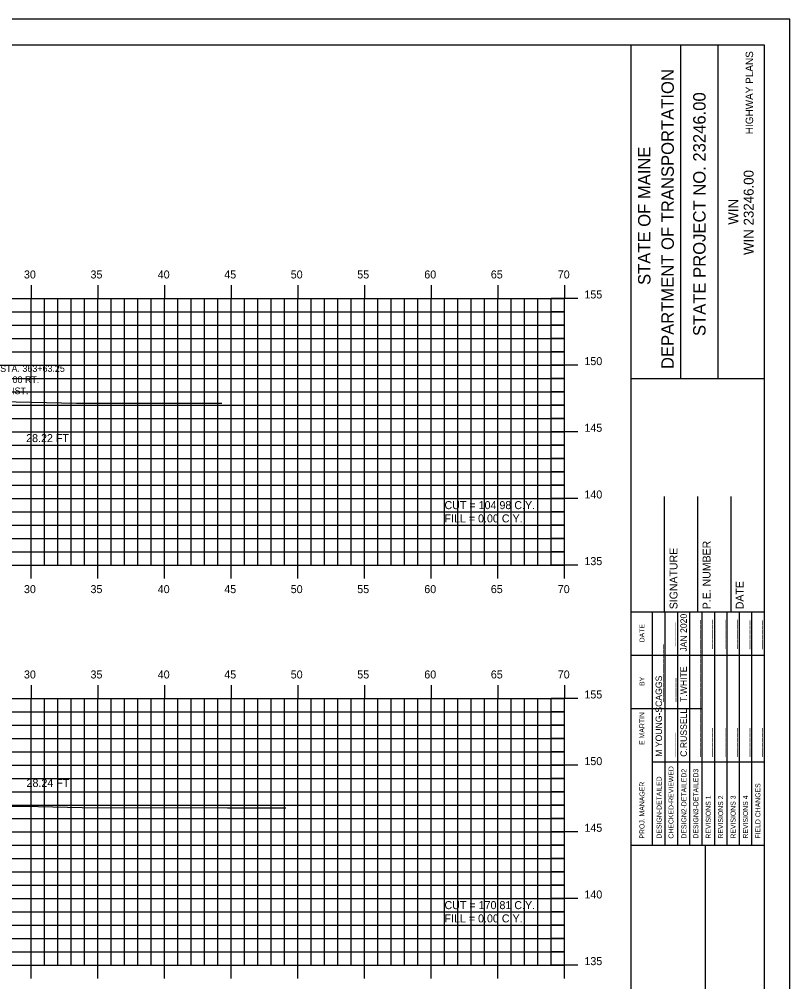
# Model space of a CAD drawing. Extents: x 1146968 to 1147138, y 608981 to 609091.
# Drawn here: x 1147080.3 to 1147138.1, y 609019.1 to 609091.3 of the extents above; entities that cross this region are included whole.
import ezdxf

# ---------------------------------------------------------------- set-up
doc = ezdxf.new("R2010")
doc.units = 0
for name, color, linetype in [('BORDER', 7, 'Continuous'), ('D_Text_Monospaced', 7, 'Continuous'), ('D_Text_Standard', 7, 'Continuous'), ('H_V ANNOTATION', 7, 'Continuous'), ('HIGHWAY_TITLE', 7, 'Continuous'), ('MAJOR', 7, 'Continuous'), ('MINOR', 7, 'Continuous'), ('PLOT BOUNDARY', 7, 'Continuous'), ('S_Roadway_Centerline', 7, 'Continuous')]:
    doc.layers.add(name, color=color, linetype=linetype)

msp = doc.modelspace()

# ---------------------------------------------------------------- linework, layer by layer
at = {"layer": 'BORDER'}
for p, q in [((1147126.185, 608984.335), (1147126.185, 609089.335)), ((1147129.913, 609064.332), (1147129.913, 609089.332)), ((1147132.708, 609064.332), (1147132.708, 609089.332)), ((1147126.185, 609064.329), (1147136.185, 609064.329)), ((1147128.685, 609046.838), (1147128.685, 609055.485)), ((1147131.185, 609046.838), (1147131.185, 609055.485)), ((1147133.685, 609046.838), (1147133.685, 609055.485)), ((1147126.185, 609046.838), (1147136.185, 609046.838)), ((1147126.185, 609029.338), (1147136.185, 609029.338)), ((1147131.776, 608994.338), (1147131.776, 609029.338))]:
    msp.add_line(p, q, dxfattribs=at)
msp.add_lwpolyline([(1146976.185, 608984.335), (1147136.185, 608984.335), (1147136.185, 609089.335), (1146976.185, 609089.335)], close=True, dxfattribs=at)
for points in [[(1147127.799, 609043.588), (1147127.799, 609046.838)], [(1147128.732, 609029.341), (1147128.732, 609046.838)], [(1147129.664, 609046.838), (1147129.664, 609029.341)], [(1147130.595, 609029.341), (1147130.595, 609046.838)], [(1147131.527, 609029.341), (1147131.527, 609046.838)], [(1147132.459, 609029.341), (1147132.459, 609046.838)], [(1147133.39, 609029.341), (1147133.39, 609046.838)], [(1147134.322, 609029.341), (1147134.322, 609046.838)], [(1147135.254, 609029.341), (1147135.254, 609046.838)], [(1147127.8, 609029.341), (1147127.8, 609046.132)], [(1147126.185, 609043.588), (1147136.185, 609043.588)], [(1147126.185, 609039.588), (1147127.8, 609039.588)], [(1147127.799, 609039.588), (1147131.526, 609039.588)], [(1147127.799, 609035.588), (1147136.185, 609035.588)]]:
    msp.add_lwpolyline(points, dxfattribs=at)
at = {"layer": 'MAJOR'}
for p, q in [((1147081.184, 609071.337), (1147081.184, 609070.335)), ((1147086.184, 609071.337), (1147086.184, 609070.335)), ((1147091.184, 609071.337), (1147091.184, 609070.335)), ((1147096.184, 609071.337), (1147096.184, 609070.335)), ((1147101.184, 609071.337), (1147101.184, 609070.335)), ((1147106.184, 609071.337), (1147106.184, 609070.335)), ((1147111.184, 609071.337), (1147111.184, 609070.335)), ((1147116.184, 609071.337), (1147116.184, 609070.335)), ((1147121.184, 609071.337), (1147121.184, 609070.335)), ((1146981.184, 609070.335), (1147121.184, 609070.335)), ((1146981.184, 609070.335), (1147121.184, 609070.335)), ((1147081.184, 609050.335), (1147081.184, 609070.335)), ((1147086.184, 609050.335), (1147086.184, 609070.335)), ((1147091.184, 609050.335), (1147091.184, 609070.335)), ((1147096.184, 609050.335), (1147096.184, 609070.335)), ((1147101.184, 609050.335), (1147101.184, 609070.335)), ((1147106.184, 609050.335), (1147106.184, 609070.335)), ((1147111.184, 609050.335), (1147111.184, 609070.335)), ((1147116.184, 609050.335), (1147116.184, 609070.335)), ((1147122.186, 609070.335), (1147120.182, 609070.335)), ((1147121.184, 609050.335), (1147121.184, 609070.335)), ((1147121.184, 609050.335), (1147121.184, 609070.335)), ((1146981.184, 609065.335), (1147121.184, 609065.335)), ((1147122.186, 609065.335), (1147120.182, 609065.335)), ((1146981.184, 609060.335), (1147121.184, 609060.335)), ((1147122.186, 609060.335), (1147120.182, 609060.335)), ((1146981.184, 609055.335), (1147121.184, 609055.335)), ((1147122.186, 609055.335), (1147120.182, 609055.335)), ((1146981.184, 609050.335), (1147121.184, 609050.335)), ((1146981.184, 609050.335), (1147121.184, 609050.335)), ((1147081.184, 609049.333), (1147081.184, 609050.335)), ((1147086.184, 609049.333), (1147086.184, 609050.335)), ((1147091.184, 609049.333), (1147091.184, 609050.335)), ((1147096.184, 609049.333), (1147096.184, 609050.335)), ((1147101.184, 609049.333), (1147101.184, 609050.335)), ((1147106.184, 609049.333), (1147106.184, 609050.335)), ((1147111.184, 609049.333), (1147111.184, 609050.335)), ((1147116.184, 609049.333), (1147116.184, 609050.335)), ((1147122.186, 609050.335), (1147120.182, 609050.335)), ((1147121.184, 609049.333), (1147121.184, 609050.335)), ((1147081.184, 609041.337), (1147081.184, 609040.335)), ((1147086.184, 609041.337), (1147086.184, 609040.335)), ((1147091.184, 609041.337), (1147091.184, 609040.335)), ((1147096.184, 609041.337), (1147096.184, 609040.335)), ((1147101.184, 609041.337), (1147101.184, 609040.335)), ((1147106.184, 609041.337), (1147106.184, 609040.335)), ((1147111.184, 609041.337), (1147111.184, 609040.335)), ((1147116.184, 609041.337), (1147116.184, 609040.335)), ((1147121.184, 609041.337), (1147121.184, 609040.335)), ((1146981.184, 609040.335), (1147121.184, 609040.335)), ((1146981.184, 609040.335), (1147121.184, 609040.335)), ((1147081.184, 609020.335), (1147081.184, 609040.335)), ((1147086.184, 609020.335), (1147086.184, 609040.335)), ((1147091.184, 609020.335), (1147091.184, 609040.335)), ((1147096.184, 609020.335), (1147096.184, 609040.335)), ((1147101.184, 609020.335), (1147101.184, 609040.335)), ((1147106.184, 609020.335), (1147106.184, 609040.335)), ((1147111.184, 609020.335), (1147111.184, 609040.335)), ((1147116.184, 609020.335), (1147116.184, 609040.335)), ((1147122.186, 609040.335), (1147120.182, 609040.335)), ((1147121.184, 609020.335), (1147121.184, 609040.335)), ((1147121.184, 609020.335), (1147121.184, 609040.335)), ((1146981.184, 609035.335), (1147121.184, 609035.335)), ((1147122.186, 609035.335), (1147120.182, 609035.335)), ((1146981.184, 609030.335), (1147121.184, 609030.335)), ((1147122.186, 609030.335), (1147120.182, 609030.335)), ((1146981.184, 609025.335), (1147121.184, 609025.335)), ((1147122.186, 609025.335), (1147120.182, 609025.335)), ((1146981.184, 609020.335), (1147121.184, 609020.335)), ((1146981.184, 609020.335), (1147121.184, 609020.335)), ((1147081.184, 609019.333), (1147081.184, 609020.335)), ((1147086.184, 609019.333), (1147086.184, 609020.335)), ((1147091.184, 609019.333), (1147091.184, 609020.335)), ((1147096.184, 609019.333), (1147096.184, 609020.335)), ((1147101.184, 609019.333), (1147101.184, 609020.335)), ((1147106.184, 609019.333), (1147106.184, 609020.335)), ((1147111.184, 609019.333), (1147111.184, 609020.335)), ((1147116.184, 609019.333), (1147116.184, 609020.335)), ((1147122.186, 609020.335), (1147120.182, 609020.335)), ((1147121.184, 609019.333), (1147121.184, 609020.335))]:
    msp.add_line(p, q, dxfattribs=at)
at = {"layer": 'MINOR'}
for p, q in [((1147082.184, 609050.335), (1147082.184, 609070.335)), ((1147083.184, 609050.335), (1147083.184, 609070.335)), ((1147084.184, 609050.335), (1147084.184, 609070.335)), ((1147085.184, 609050.335), (1147085.184, 609070.335)), ((1147087.184, 609050.335), (1147087.184, 609070.335)), ((1147088.184, 609050.335), (1147088.184, 609070.335)), ((1147089.184, 609050.335), (1147089.184, 609070.335)), ((1147090.184, 609050.335), (1147090.184, 609070.335)), ((1147092.184, 609050.335), (1147092.184, 609070.335)), ((1147093.184, 609050.335), (1147093.184, 609070.335)), ((1147094.184, 609050.335), (1147094.184, 609070.335)), ((1147095.184, 609050.335), (1147095.184, 609070.335)), ((1147097.184, 609050.335), (1147097.184, 609070.335)), ((1147098.184, 609050.335), (1147098.184, 609070.335)), ((1147099.184, 609050.335), (1147099.184, 609070.335)), ((1147100.184, 609050.335), (1147100.184, 609070.335)), ((1147102.184, 609050.335), (1147102.184, 609070.335)), ((1147103.184, 609050.335), (1147103.184, 609070.335)), ((1147104.184, 609050.335), (1147104.184, 609070.335)), ((1147105.184, 609050.335), (1147105.184, 609070.335)), ((1147107.184, 609050.335), (1147107.184, 609070.335)), ((1147108.184, 609050.335), (1147108.184, 609070.335)), ((1147109.184, 609050.335), (1147109.184, 609070.335)), ((1147110.184, 609050.335), (1147110.184, 609070.335)), ((1147112.184, 609050.335), (1147112.184, 609070.335)), ((1147113.184, 609050.335), (1147113.184, 609070.335)), ((1147114.184, 609050.335), (1147114.184, 609070.335)), ((1147115.184, 609050.335), (1147115.184, 609070.335)), ((1147117.184, 609050.335), (1147117.184, 609070.335)), ((1147118.184, 609050.335), (1147118.184, 609070.335)), ((1147119.184, 609050.335), (1147119.184, 609070.335)), ((1147120.184, 609050.335), (1147120.184, 609070.335)), ((1146981.184, 609069.335), (1147121.184, 609069.335)), ((1147121.184, 609069.335), (1147120.182, 609069.335)), ((1146981.184, 609068.335), (1147121.184, 609068.335)), ((1147121.184, 609068.335), (1147120.182, 609068.335)), ((1146981.184, 609067.335), (1147121.184, 609067.335)), ((1147121.184, 609067.335), (1147120.182, 609067.335)), ((1146981.184, 609066.335), (1147121.184, 609066.335)), ((1147121.184, 609066.335), (1147120.182, 609066.335)), ((1146981.184, 609064.335), (1147121.184, 609064.335)), ((1147121.184, 609064.335), (1147120.182, 609064.335)), ((1146981.184, 609063.335), (1147121.184, 609063.335)), ((1147121.184, 609063.335), (1147120.182, 609063.335)), ((1146981.184, 609062.335), (1147121.184, 609062.335)), ((1147121.184, 609062.335), (1147120.182, 609062.335)), ((1146981.184, 609061.335), (1147121.184, 609061.335)), ((1147121.184, 609061.335), (1147120.182, 609061.335)), ((1146981.184, 609059.335), (1147121.184, 609059.335)), ((1147121.184, 609059.335), (1147120.182, 609059.335)), ((1146981.184, 609058.335), (1147121.184, 609058.335)), ((1147121.184, 609058.335), (1147120.182, 609058.335)), ((1146981.184, 609057.335), (1147121.184, 609057.335)), ((1147121.184, 609057.335), (1147120.182, 609057.335)), ((1146981.184, 609056.335), (1147121.184, 609056.335)), ((1147121.184, 609056.335), (1147120.182, 609056.335)), ((1146981.184, 609054.335), (1147121.184, 609054.335)), ((1147121.184, 609054.335), (1147120.182, 609054.335)), ((1146981.184, 609053.335), (1147121.184, 609053.335)), ((1147121.184, 609053.335), (1147120.182, 609053.335)), ((1146981.184, 609052.335), (1147121.184, 609052.335)), ((1147121.184, 609052.335), (1147120.182, 609052.335)), ((1146981.184, 609051.335), (1147121.184, 609051.335)), ((1147121.184, 609051.335), (1147120.182, 609051.335)), ((1147082.184, 609020.335), (1147082.184, 609040.335)), ((1147083.184, 609020.335), (1147083.184, 609040.335)), ((1147084.184, 609020.335), (1147084.184, 609040.335)), ((1147085.184, 609020.335), (1147085.184, 609040.335)), ((1147087.184, 609020.335), (1147087.184, 609040.335)), ((1147088.184, 609020.335), (1147088.184, 609040.335)), ((1147089.184, 609020.335), (1147089.184, 609040.335)), ((1147090.184, 609020.335), (1147090.184, 609040.335)), ((1147092.184, 609020.335), (1147092.184, 609040.335)), ((1147093.184, 609020.335), (1147093.184, 609040.335)), ((1147094.184, 609020.335), (1147094.184, 609040.335)), ((1147095.184, 609020.335), (1147095.184, 609040.335)), ((1147097.184, 609020.335), (1147097.184, 609040.335)), ((1147098.184, 609020.335), (1147098.184, 609040.335)), ((1147099.184, 609020.335), (1147099.184, 609040.335)), ((1147100.184, 609020.335), (1147100.184, 609040.335)), ((1147102.184, 609020.335), (1147102.184, 609040.335)), ((1147103.184, 609020.335), (1147103.184, 609040.335)), ((1147104.184, 609020.335), (1147104.184, 609040.335)), ((1147105.184, 609020.335), (1147105.184, 609040.335)), ((1147107.184, 609020.335), (1147107.184, 609040.335)), ((1147108.184, 609020.335), (1147108.184, 609040.335)), ((1147109.184, 609020.335), (1147109.184, 609040.335)), ((1147110.184, 609020.335), (1147110.184, 609040.335)), ((1147112.184, 609020.335), (1147112.184, 609040.335)), ((1147113.184, 609020.335), (1147113.184, 609040.335)), ((1147114.184, 609020.335), (1147114.184, 609040.335)), ((1147115.184, 609020.335), (1147115.184, 609040.335)), ((1147117.184, 609020.335), (1147117.184, 609040.335)), ((1147118.184, 609020.335), (1147118.184, 609040.335)), ((1147119.184, 609020.335), (1147119.184, 609040.335)), ((1147120.184, 609020.335), (1147120.184, 609040.335)), ((1146981.184, 609039.335), (1147121.184, 609039.335)), ((1147121.184, 609039.335), (1147120.182, 609039.335)), ((1146981.184, 609038.335), (1147121.184, 609038.335)), ((1147121.184, 609038.335), (1147120.182, 609038.335)), ((1146981.184, 609037.335), (1147121.184, 609037.335)), ((1147121.184, 609037.335), (1147120.182, 609037.335)), ((1146981.184, 609036.335), (1147121.184, 609036.335)), ((1147121.184, 609036.335), (1147120.182, 609036.335)), ((1146981.184, 609034.335), (1147121.184, 609034.335)), ((1147121.184, 609034.335), (1147120.182, 609034.335)), ((1146981.184, 609033.335), (1147121.184, 609033.335)), ((1147121.184, 609033.335), (1147120.182, 609033.335)), ((1146981.184, 609032.335), (1147121.184, 609032.335)), ((1147121.184, 609032.335), (1147120.182, 609032.335)), ((1146981.184, 609031.335), (1147121.184, 609031.335)), ((1147121.184, 609031.335), (1147120.182, 609031.335)), ((1146981.184, 609029.335), (1147121.184, 609029.335)), ((1147121.184, 609029.335), (1147120.182, 609029.335)), ((1146981.184, 609028.335), (1147121.184, 609028.335)), ((1147121.184, 609028.335), (1147120.182, 609028.335)), ((1146981.184, 609027.335), (1147121.184, 609027.335)), ((1147121.184, 609027.335), (1147120.182, 609027.335)), ((1146981.184, 609026.335), (1147121.184, 609026.335)), ((1147121.184, 609026.335), (1147120.182, 609026.335)), ((1146981.184, 609024.335), (1147121.184, 609024.335)), ((1147121.184, 609024.335), (1147120.182, 609024.335)), ((1146981.184, 609023.335), (1147121.184, 609023.335)), ((1147121.184, 609023.335), (1147120.182, 609023.335)), ((1146981.184, 609022.335), (1147121.184, 609022.335)), ((1147121.184, 609022.335), (1147120.182, 609022.335)), ((1146981.184, 609021.335), (1147121.184, 609021.335)), ((1147121.184, 609021.335), (1147120.182, 609021.335))]:
    msp.add_line(p, q, dxfattribs=at)
at = {"layer": 'PLOT BOUNDARY'}
msp.add_lwpolyline([(1146968.091, 608981.276), (1147138.091, 608981.276), (1147138.091, 609091.276), (1146968.091, 609091.276)], close=True, dxfattribs=at)
at = {"layer": 'S_Roadway_Centerline'}
for points in [[(1147078.913, 609062.615), (1147084.574, 609062.494), (1147087.898, 609062.485), (1147095.472, 609062.475)], [(1147074.477, 609032.306), (1147081.694, 609032.225), (1147084.988, 609032.154), (1147095.893, 609032.125), (1147100.288, 609032.12)]]:
    msp.add_lwpolyline(points, dxfattribs=at)

# ---------------------------------------------------------------- texts
at = {"layer": 'BORDER'}
for s, height, p in [('DEPARTMENT OF TRANSPORTATION', 0.93176, (1147129.391, 609065.041)), ('STATE PROJECT NO. 23246.00', 0.93176, (1147131.776, 609067.517)), ('STATE OF MAINE', 0.93176, (1147127.64, 609071.347)), ('WIN 23246.00', 0.74527, (1147135.38, 609073.596)), ('WIN', 0.7453, (1147134.221, 609075.865)), ('SIGNATURE', 0.5906, (1147129.665, 609047.03)), ('P.E. NUMBER', 0.59055, (1147132.145, 609047.03)), ('DATE', 0.5906, (1147134.626, 609047.03)), ('JAN 2020', 0.4845, (1147130.371, 609043.843)), ('DATE', 0.3714, (1147127.189, 609044.544)), ('_____', 0.4845, (1147129.402, 609044.243)), ('______', 0.4845, (1147131.265, 609044.063)), ('______', 0.4845, (1147132.197, 609044.065)), ('______', 0.4845, (1147133.129, 609044.067)), ('______', 0.4845, (1147134.06, 609044.067)), ('______', 0.4845, (1147134.992, 609044.036)), ('______', 0.4845, (1147135.924, 609044.036)), ('____________', 0.48455, (1147128.507, 609040.073)), ('____________', 0.48455, (1147131.265, 609040.073)), ('T.WHITE', 0.4845, (1147130.371, 609040.073)), ('BY', 0.3714, (1147127.189, 609041.273)), ('M YOUNG-SCAGGS', 0.48455, (1147128.507, 609035.961)), ('_____', 0.4845, (1147129.439, 609040.073)), ('____________', 0.48455, (1147131.265, 609035.961)), ('C.RUSSELL', 0.4845, (1147130.371, 609035.961)), ('E MARTIN', 0.3727, (1147127.189, 609036.855)), ('_____', 0.4845, (1147129.402, 609035.961)), ('______', 0.4845, (1147132.197, 609035.961)), ('______', 0.4845, (1147133.129, 609035.961)), ('______', 0.4845, (1147134.06, 609035.961)), ('______', 0.4845, (1147134.992, 609035.961)), ('______', 0.4845, (1147135.924, 609035.961)), ('CHECKED-REVIEWED', 0.37275, (1147129.366, 609029.826)), ('DESIGN2-DETAILED2', 0.37275, (1147130.335, 609029.826)), ('DESIGN3-DETAILED3', 0.37275, (1147131.229, 609029.826)), ('DESIGN-DETAILED', 0.37275, (1147128.471, 609029.826)), ('PROJ. MANAGER', 0.37275, (1147127.189, 609029.826)), ('FIELD CHANGES', 0.37275, (1147135.887, 609029.826)), ('REVISIONS 1', 0.37275, (1147132.161, 609029.826)), ('REVISIONS 2', 0.37275, (1147133.092, 609029.826)), ('REVISIONS 3', 0.37275, (1147134.024, 609029.826)), ('REVISIONS 4', 0.37275, (1147134.956, 609029.826))]:
    msp.add_text(s, height=height, rotation=90, dxfattribs=at).set_placement(p)
at = {"layer": 'D_Text_Monospaced'}
for s, height, p in [('STA. 363+63.25', 0.49998, (1147078.847, 609064.83)), ('26.00 RT.', 0.5, (1147078.847, 609063.996)), ('EXIST. ', 0.5, (1147078.847, 609063.156))]:
    msp.add_text(s, height=height, dxfattribs=at).set_placement(p)
at = {"layer": 'D_Text_Standard'}
for s, p in [('28.22 FT', (1147080.795, 609059.561)), ('CUT = 104.98 C.Y.', (1147112.184, 609054.535)), ('FILL = 0.00 C.Y.', (1147112.184, 609053.539)), ('28.24 FT', (1147080.826, 609033.697)), ('CUT = 170.81 C.Y.', (1147112.184, 609024.535)), ('FILL = 0.00 C.Y.', (1147112.184, 609023.539))]:
    msp.add_text(s, height=0.6, dxfattribs=at).set_placement(p)
at = {"layer": 'H_V ANNOTATION'}
for s, p in [('30', (1147080.633, 609071.835)), ('35', (1147085.625, 609071.835)), ('40', (1147090.671, 609071.835)), ('45', (1147095.662, 609071.835)), ('50', (1147100.649, 609071.835)), ('55', (1147105.641, 609071.835)), ('60', (1147110.671, 609071.835)), ('65', (1147115.662, 609071.835)), ('70', (1147120.686, 609071.835)), ('155', (1147122.684, 609070.335)), ('150', (1147122.684, 609065.335)), ('145', (1147122.684, 609060.335)), ('140', (1147122.684, 609055.335)), ('135', (1147122.684, 609050.335)), ('30', (1147080.633, 609048.235)), ('35', (1147085.625, 609048.235)), ('40', (1147090.671, 609048.235)), ('45', (1147095.662, 609048.235)), ('50', (1147100.649, 609048.235)), ('55', (1147105.641, 609048.235)), ('60', (1147110.671, 609048.235)), ('65', (1147115.662, 609048.235)), ('70', (1147120.686, 609048.235)), ('30', (1147080.633, 609041.835)), ('35', (1147085.625, 609041.835)), ('40', (1147090.671, 609041.835)), ('45', (1147095.662, 609041.835)), ('50', (1147100.649, 609041.835)), ('55', (1147105.641, 609041.835)), ('60', (1147110.671, 609041.835)), ('65', (1147115.662, 609041.835)), ('70', (1147120.686, 609041.835)), ('155', (1147122.684, 609040.335)), ('150', (1147122.684, 609035.335)), ('145', (1147122.684, 609030.335)), ('140', (1147122.684, 609025.335)), ('135', (1147122.684, 609020.335))]:
    msp.add_text(s, height=0.6, dxfattribs=at).set_placement(p)
at = {"layer": 'HIGHWAY_TITLE'}
msp.add_text('HIGHWAY PLANS', height=0.55901, rotation=90, dxfattribs=at).set_placement((1147135.343, 609082.65))

doc.saveas('drawing.dxf')
